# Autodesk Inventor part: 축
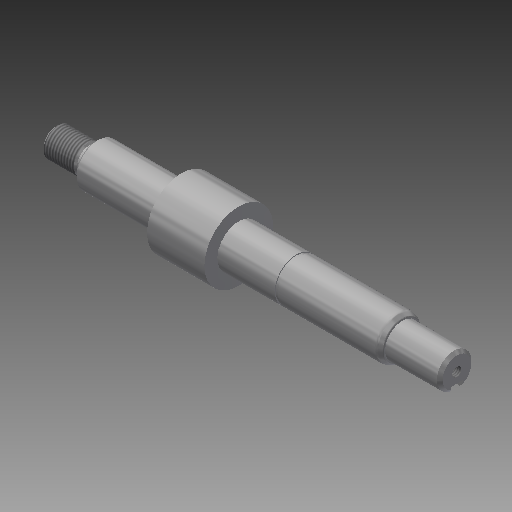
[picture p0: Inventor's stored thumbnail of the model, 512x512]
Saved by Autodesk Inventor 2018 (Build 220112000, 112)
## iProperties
Created: 2016-08
Part Number: 축
Material: 강철, 탄소
Document SubType Name: Modeling
Designer: mduedu
Density: 7.87 g/cm^3
Appearance: 강철
Author: mduedu
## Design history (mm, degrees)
sketch "스케치1"
  geometry: L1 (-70, 0)-(70, 0); L2 (-70, 0)-(-70, 5); L3 (-70, 5)-(-56, 5); L4 (-56, 5)-(-56, 7.5); L5 (-56, 7.5)-(49.355, 7.5); L6 (51, 7.5)-(51, 6.55); L7 (51, 6)-(70, 6); L8 (70, 6)-(70, 0); L9 (51, 6.55)-(49.355, 7.5); L10 (49.355, 7.5)-(51, 7.5); L11 (51, 6.55)-(51, 6); 2 further points
  constraints: 22 end point, 7 parallel, 2 perpendicular, 1 coincident, 1 horizontal, 1 midpoint
  dimensions: "d0" = 140 distance of L1.start L1.end; "d2" = 14 distance of L2.end L3.end; "d3" = 19 distance of L7.start L7.end; "d4" = 10 diameter of L3 L1; "d5" = 15 diameter of L5 L1; "d6" = 12 diameter of L7 L1; "d63" = 13.1 diameter of L6.end L1; "d64" = 30 deg angle of L5 L9
revolve "회전1" sketch "스케치1" stored, may be unused: angle "d7" = 90 deg
sketch "스케치2"
  geometry: L1 (-56, -5)-(-56, 5) reference; L2 (70, -6)-(70, 6) reference; L3 (-56, 0)-(70, 0); L4 (-58, 4.5)-(-58, 5); L5 (-58, 5)-(-56, 5); L6 (-56, 5)-(-56, 4.5); L7 (-58, 4.5)-(-56, 4.5); 1 further point
  constraints: 10 end point, 2 midpoint, 1 parallel, 1 perpendicular, 1 point on line
  dimensions: "d8" = 2 distance of L4.end L5.end; "d10" = 10 diameter of L5 L3; "d11" = 9 diameter of L7 L3
revolve "회전2" sketch "스케치2" stored, may be unused: angle "d12" = 90 deg
node "작업 평면1"
sketch "스케치3"
  geometry: C1 r 12 at (0, 0); 1 further point
  constraints: 1 centre point, 1 coincident
  dimensions: "d15" = 24 diameter of C1
extrude "돌출1" join sketch "스케치3" distance "d16" = 20; taper "d17" = 0 deg
sketch "스케치5"
  geometry: L1 (-70, -5)-(-70, 5) reference; L2 (70, -6)-(70, 6) reference; L3 (-70, 0)-(70, 0); L4 (-6, 7.5)-(49.355, 7.5) reference; L5 (15.15, 7.5)-(14, 7.5); L6 (14, 7.5)-(14, 7.15); L7 (14, 7.15)-(15.15, 7.15); L8 (15.15, 7.15)-(15.15, 7.5); 1 further point
  constraints: 10 end point, 2 midpoint, 2 parallel, 1 horizontal, 1 perpendicular, 1 point on line
  dimensions: "d19" = 56 distance between parallel lines of L6 L2; "d20" = 1.15 distance between parallel lines of L8 L6; "d21" = 14.3 diameter of L7 L3
revolve "회전3" sketch "스케치5" stored, may be unused: angle "d22" = 90 deg
node "작업 평면3"
sketch "스케치6"
  geometry: L1 (6.5, 2)-(-9.5, 2); L2 (-9.5, 2)-(-9.5, -2); L3 (-9.5, -2)-(6.5, -2); L4 (-9.5, 6)-(-9.5, -6) reference; A1 r 2 centre (6.5, 0) between (6.5, -2) and (6.5, 2); 2 further points
  constraints: 6 end point, 2 midpoint, 2 point on circle, 2 tangent, 1 centre point, 1 horizontal, 1 horizontal alignment, 1 parallel, 1 perpendicular
  dimensions: "d23" = 4 distance between parallel lines of L3 L1; "d62" = 18 dimension on A1 L2
extrude "돌출2" cut sketch "스케치6" distance "d25" = 2.5; taper "d26" = 0 deg
feature "스레드1" dims "d27" = 10, "d28" = 0
fillet "모깎기1" dims "d65" = 2
fillet "모깎기2" dims "d66" = 0.5
chamfer "모따기5" distance "d41" = 0.5; stored, may be unused: second distance "d42" = 2, angle "d43" = 45 deg
chamfer "모따기7" distance "d47" = 1; stored, may be unused: second distance "d48" = 2, angle "d49" = 45 deg
chamfer "모따기8" distance "d50" = 1; stored, may be unused: second distance "d51" = 2, angle "d52" = 45 deg
sketch "스케치8"
  geometry: 1 further point
hole "구멍1" sketch "스케치8" at (2, 3.5) diameter "d53" = 3.242; stored, may be unused: countersink angle "d57" = 90 deg, drill point angle "d59" = 120 deg; dims "d54" = 10, "d55" = 4, "d56" = 2, "d58" = 12
node "솔리드1"
other parameters: "d13" = -44
